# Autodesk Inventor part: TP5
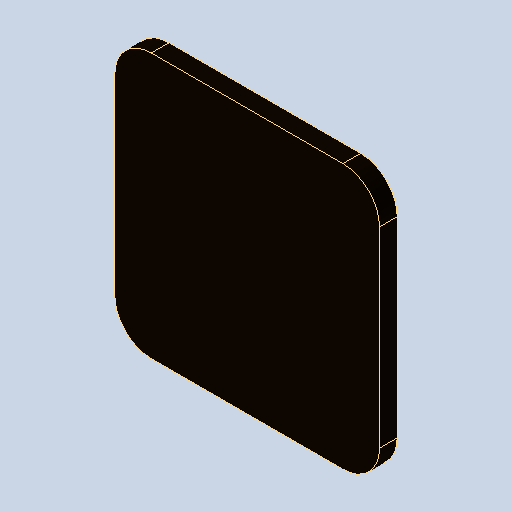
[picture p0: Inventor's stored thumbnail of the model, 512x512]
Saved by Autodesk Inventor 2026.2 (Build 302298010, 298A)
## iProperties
Created: 2026-10
Part Number: TP5
Material: Générique
Document SubType Name: Modeling
Designer: mel
Density: 1 g/cm^3
Appearance: Par défaut
Author: mel
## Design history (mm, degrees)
feature "Base1"
node "Solide1"
